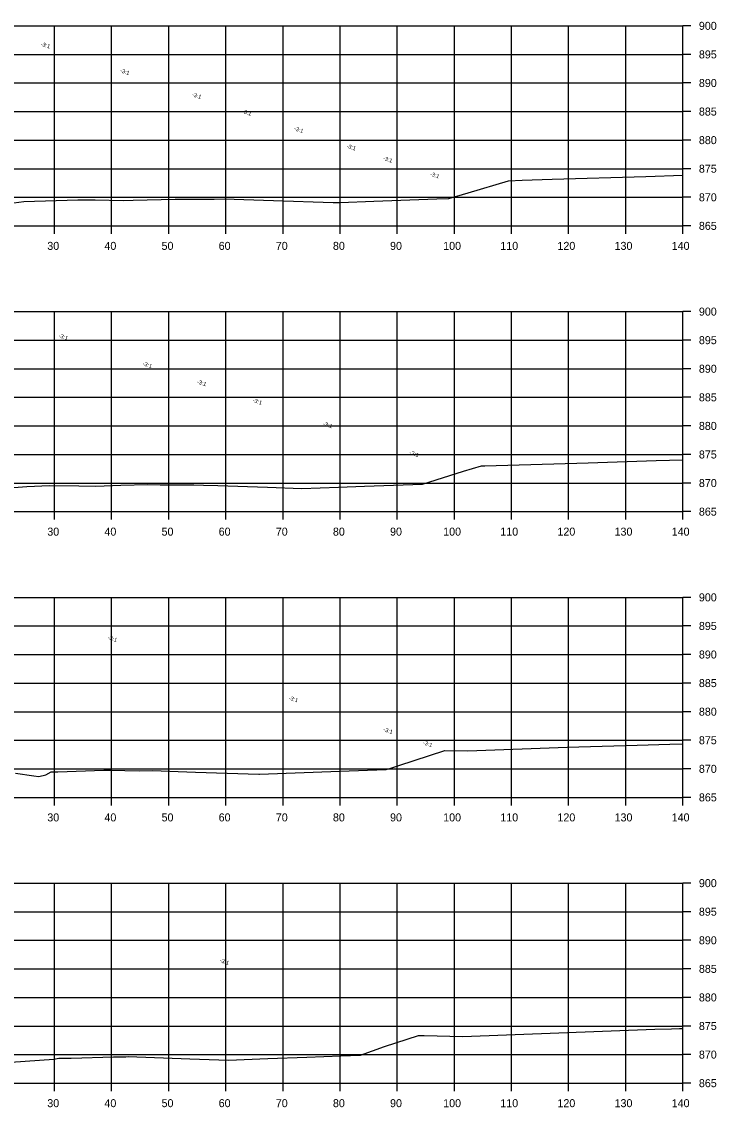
# Model space of a CAD drawing. Extents: x 1098669 to 1198896, y 698679 to 704410.
# Drawn here: x 1110915.5 to 1111037, y 704218 to 704407.9 of the extents above; entities that cross this region are included whole.
import ezdxf

# ---------------------------------------------------------------- set-up
doc = ezdxf.new("R2010")
doc.units = 0
for name, color, linetype in [('R_Axis', 7, 'Continuous'), ('R_Axis Annot', 7, 'Continuous'), ('R_Grid', 7, 'Continuous'), ('R_No Plot', 7, 'Continuous'), ('R_Xsect Slope', 7, 'Continuous')]:
    doc.layers.add(name, color=color, linetype=linetype)

msp = doc.modelspace()

# ---------------------------------------------------------------- linework, layer by layer
at = {"layer": 'R_Axis'}
for p, q in [((1111031.2, 704372.22), (1111031.2, 704407.22)), ((1111032.6, 704407.22), (1111031.2, 704407.22)), ((1111032.6, 704402.22), (1111031.2, 704402.22)), ((1111032.6, 704397.22), (1111031.2, 704397.22)), ((1111032.6, 704392.22), (1111031.2, 704392.22)), ((1111032.6, 704387.22), (1111031.2, 704387.22)), ((1111032.6, 704382.22), (1111031.2, 704382.22)), ((1111032.6, 704377.22), (1111031.2, 704377.22)), ((1110751.2, 704372.22), (1111031.2, 704372.22)), ((1110921.2, 704370.82), (1110921.2, 704372.22)), ((1110931.2, 704370.82), (1110931.2, 704372.22)), ((1110941.2, 704370.82), (1110941.2, 704372.22)), ((1110951.2, 704370.82), (1110951.2, 704372.22)), ((1110961.2, 704370.82), (1110961.2, 704372.22)), ((1110971.2, 704370.82), (1110971.2, 704372.22)), ((1110981.2, 704370.82), (1110981.2, 704372.22)), ((1110991.2, 704370.82), (1110991.2, 704372.22)), ((1111001.2, 704370.82), (1111001.2, 704372.22)), ((1111011.2, 704370.82), (1111011.2, 704372.22)), ((1111021.2, 704370.82), (1111021.2, 704372.22)), ((1111031.2, 704370.82), (1111031.2, 704372.22)), ((1111032.6, 704372.22), (1111031.2, 704372.22)), ((1111031.2, 704322.22), (1111031.2, 704357.22)), ((1111032.6, 704357.22), (1111031.2, 704357.22)), ((1111032.6, 704352.22), (1111031.2, 704352.22)), ((1111032.6, 704347.22), (1111031.2, 704347.22)), ((1111032.6, 704342.22), (1111031.2, 704342.22)), ((1111032.6, 704337.22), (1111031.2, 704337.22)), ((1111032.6, 704332.22), (1111031.2, 704332.22)), ((1111032.6, 704327.22), (1111031.2, 704327.22)), ((1110751.2, 704322.22), (1111031.2, 704322.22)), ((1110921.2, 704320.82), (1110921.2, 704322.22)), ((1110931.2, 704320.82), (1110931.2, 704322.22)), ((1110941.2, 704320.82), (1110941.2, 704322.22)), ((1110951.2, 704320.82), (1110951.2, 704322.22)), ((1110961.2, 704320.82), (1110961.2, 704322.22)), ((1110971.2, 704320.82), (1110971.2, 704322.22)), ((1110981.2, 704320.82), (1110981.2, 704322.22)), ((1110991.2, 704320.82), (1110991.2, 704322.22)), ((1111001.2, 704320.82), (1111001.2, 704322.22)), ((1111011.2, 704320.82), (1111011.2, 704322.22)), ((1111021.2, 704320.82), (1111021.2, 704322.22)), ((1111031.2, 704320.82), (1111031.2, 704322.22)), ((1111032.6, 704322.22), (1111031.2, 704322.22)), ((1111031.2, 704272.22), (1111031.2, 704307.22)), ((1111032.6, 704307.22), (1111031.2, 704307.22)), ((1111032.6, 704302.22), (1111031.2, 704302.22)), ((1111032.6, 704297.22), (1111031.2, 704297.22)), ((1111032.6, 704292.22), (1111031.2, 704292.22)), ((1111032.6, 704287.22), (1111031.2, 704287.22)), ((1111032.6, 704282.22), (1111031.2, 704282.22)), ((1111032.6, 704277.22), (1111031.2, 704277.22)), ((1110751.2, 704272.22), (1111031.2, 704272.22)), ((1110921.2, 704270.82), (1110921.2, 704272.22)), ((1110931.2, 704270.82), (1110931.2, 704272.22)), ((1110941.2, 704270.82), (1110941.2, 704272.22)), ((1110951.2, 704270.82), (1110951.2, 704272.22)), ((1110961.2, 704270.82), (1110961.2, 704272.22)), ((1110971.2, 704270.82), (1110971.2, 704272.22)), ((1110981.2, 704270.82), (1110981.2, 704272.22)), ((1110991.2, 704270.82), (1110991.2, 704272.22)), ((1111001.2, 704270.82), (1111001.2, 704272.22)), ((1111011.2, 704270.82), (1111011.2, 704272.22)), ((1111021.2, 704270.82), (1111021.2, 704272.22)), ((1111031.2, 704270.82), (1111031.2, 704272.22)), ((1111032.6, 704272.22), (1111031.2, 704272.22)), ((1111031.2, 704222.22), (1111031.2, 704257.22)), ((1111032.6, 704257.22), (1111031.2, 704257.22)), ((1111032.6, 704252.22), (1111031.2, 704252.22)), ((1111032.6, 704247.22), (1111031.2, 704247.22)), ((1111032.6, 704242.22), (1111031.2, 704242.22)), ((1111032.6, 704237.22), (1111031.2, 704237.22)), ((1111032.6, 704232.22), (1111031.2, 704232.22)), ((1111032.6, 704227.22), (1111031.2, 704227.22)), ((1110751.2, 704222.22), (1111031.2, 704222.22)), ((1110921.2, 704220.82), (1110921.2, 704222.22)), ((1110931.2, 704220.82), (1110931.2, 704222.22)), ((1110941.2, 704220.82), (1110941.2, 704222.22)), ((1110951.2, 704220.82), (1110951.2, 704222.22)), ((1110961.2, 704220.82), (1110961.2, 704222.22)), ((1110971.2, 704220.82), (1110971.2, 704222.22)), ((1110981.2, 704220.82), (1110981.2, 704222.22)), ((1110991.2, 704220.82), (1110991.2, 704222.22)), ((1111001.2, 704220.82), (1111001.2, 704222.22)), ((1111011.2, 704220.82), (1111011.2, 704222.22)), ((1111021.2, 704220.82), (1111021.2, 704222.22)), ((1111031.2, 704220.82), (1111031.2, 704222.22)), ((1111032.6, 704222.22), (1111031.2, 704222.22))]:
    msp.add_line(p, q, dxfattribs=at)
at = {"layer": 'R_Grid'}
for p, q in [((1110751.2, 704407.22), (1111031.2, 704407.22)), ((1110921.2, 704372.22), (1110921.2, 704407.22)), ((1110931.2, 704372.22), (1110931.2, 704407.22)), ((1110941.2, 704372.22), (1110941.2, 704407.22)), ((1110951.2, 704372.22), (1110951.2, 704407.22)), ((1110961.2, 704372.22), (1110961.2, 704407.22)), ((1110971.2, 704372.22), (1110971.2, 704407.22)), ((1110981.2, 704372.22), (1110981.2, 704407.22)), ((1110991.2, 704372.22), (1110991.2, 704407.22)), ((1111001.2, 704372.22), (1111001.2, 704407.22)), ((1111011.2, 704372.22), (1111011.2, 704407.22)), ((1111021.2, 704372.22), (1111021.2, 704407.22)), ((1111031.2, 704372.22), (1111031.2, 704407.22)), ((1110751.2, 704402.22), (1111031.2, 704402.22)), ((1110751.2, 704397.22), (1111031.2, 704397.22)), ((1110751.2, 704392.22), (1111031.2, 704392.22)), ((1110751.2, 704387.22), (1111031.2, 704387.22)), ((1110751.2, 704382.22), (1111031.2, 704382.22)), ((1110751.2, 704377.22), (1111031.2, 704377.22)), ((1110751.2, 704372.22), (1111031.2, 704372.22)), ((1110751.2, 704357.22), (1111031.2, 704357.22)), ((1110921.2, 704322.22), (1110921.2, 704357.22)), ((1110931.2, 704322.22), (1110931.2, 704357.22)), ((1110941.2, 704322.22), (1110941.2, 704357.22)), ((1110951.2, 704322.22), (1110951.2, 704357.22)), ((1110961.2, 704322.22), (1110961.2, 704357.22)), ((1110971.2, 704322.22), (1110971.2, 704357.22)), ((1110981.2, 704322.22), (1110981.2, 704357.22)), ((1110991.2, 704322.22), (1110991.2, 704357.22)), ((1111001.2, 704322.22), (1111001.2, 704357.22)), ((1111011.2, 704322.22), (1111011.2, 704357.22)), ((1111021.2, 704322.22), (1111021.2, 704357.22)), ((1111031.2, 704322.22), (1111031.2, 704357.22)), ((1110751.2, 704352.22), (1111031.2, 704352.22)), ((1110751.2, 704347.22), (1111031.2, 704347.22)), ((1110751.2, 704342.22), (1111031.2, 704342.22)), ((1110751.2, 704337.22), (1111031.2, 704337.22)), ((1110751.2, 704332.22), (1111031.2, 704332.22)), ((1110751.2, 704327.22), (1111031.2, 704327.22)), ((1110751.2, 704322.22), (1111031.2, 704322.22)), ((1110751.2, 704307.22), (1111031.2, 704307.22)), ((1110921.2, 704272.22), (1110921.2, 704307.22)), ((1110931.2, 704272.22), (1110931.2, 704307.22)), ((1110941.2, 704272.22), (1110941.2, 704307.22)), ((1110951.2, 704272.22), (1110951.2, 704307.22)), ((1110961.2, 704272.22), (1110961.2, 704307.22)), ((1110971.2, 704272.22), (1110971.2, 704307.22)), ((1110981.2, 704272.22), (1110981.2, 704307.22)), ((1110991.2, 704272.22), (1110991.2, 704307.22)), ((1111001.2, 704272.22), (1111001.2, 704307.22)), ((1111011.2, 704272.22), (1111011.2, 704307.22)), ((1111021.2, 704272.22), (1111021.2, 704307.22)), ((1111031.2, 704272.22), (1111031.2, 704307.22)), ((1110751.2, 704302.22), (1111031.2, 704302.22)), ((1110751.2, 704297.22), (1111031.2, 704297.22)), ((1110751.2, 704292.22), (1111031.2, 704292.22)), ((1110751.2, 704287.22), (1111031.2, 704287.22)), ((1110751.2, 704282.22), (1111031.2, 704282.22)), ((1110751.2, 704277.22), (1111031.2, 704277.22)), ((1110751.2, 704272.22), (1111031.2, 704272.22)), ((1110751.2, 704257.22), (1111031.2, 704257.22)), ((1110921.2, 704222.22), (1110921.2, 704257.22)), ((1110931.2, 704222.22), (1110931.2, 704257.22)), ((1110941.2, 704222.22), (1110941.2, 704257.22)), ((1110951.2, 704222.22), (1110951.2, 704257.22)), ((1110961.2, 704222.22), (1110961.2, 704257.22)), ((1110971.2, 704222.22), (1110971.2, 704257.22)), ((1110981.2, 704222.22), (1110981.2, 704257.22)), ((1110991.2, 704222.22), (1110991.2, 704257.22)), ((1111001.2, 704222.22), (1111001.2, 704257.22)), ((1111011.2, 704222.22), (1111011.2, 704257.22)), ((1111021.2, 704222.22), (1111021.2, 704257.22)), ((1111031.2, 704222.22), (1111031.2, 704257.22)), ((1110751.2, 704252.22), (1111031.2, 704252.22)), ((1110751.2, 704247.22), (1111031.2, 704247.22)), ((1110751.2, 704242.22), (1111031.2, 704242.22)), ((1110751.2, 704237.22), (1111031.2, 704237.22)), ((1110751.2, 704232.22), (1111031.2, 704232.22)), ((1110751.2, 704227.22), (1111031.2, 704227.22)), ((1110751.2, 704222.22), (1111031.2, 704222.22))]:
    msp.add_line(p, q, dxfattribs=at)
at = {"layer": 'R_No Plot'}
for points in [[(1110914.08, 704376.25), (1110915.86, 704376.49), (1110925.3, 704376.79), (1110928.29, 704376.77), (1110933.26, 704376.66), (1110934.99, 704376.73), (1110942.33, 704376.91), (1110942.39, 704376.9), (1110942.73, 704376.91), (1110949.15, 704376.9), (1110950.89, 704376.93), (1110959.54, 704376.64), (1110969.96, 704376.29), (1110970.7, 704376.32), (1110971.23, 704376.33), (1110977.12, 704376.54), (1110988.13, 704376.95), (1110990.24, 704377.01), (1110993.64, 704377.99), (1111000.67, 704380.09), (1111003.08, 704380.22), (1111008.32, 704380.37), (1111024.74, 704380.88), (1111031.2, 704381.1)], [(1110914.07, 704326.47), (1110915.58, 704326.54), (1110916.33, 704326.64), (1110920.32, 704326.77), (1110925.46, 704326.73), (1110928.42, 704326.67), (1110932.81, 704326.83), (1110937.54, 704326.95), (1110939.71, 704326.9), (1110945.6, 704326.92), (1110947.28, 704326.86), (1110949.78, 704326.78), (1110958.47, 704326.48), (1110964.47, 704326.28), (1110970.9, 704326.52), (1110975.46, 704326.68), (1110985.6, 704327.04), (1110992.82, 704329.29), (1110995.95, 704330.23), (1110996.55, 704330.26), (1111014.59, 704330.78), (1111026.5, 704331.15), (1111031.2, 704331.31)], [(1110914.39, 704276.47), (1110917.59, 704276), (1110918.48, 704275.87), (1110919.69, 704276.16), (1110920.64, 704276.69), (1110921.6, 704276.68), (1110921.81, 704276.68), (1110929.83, 704276.97), (1110931, 704277), (1110936.04, 704276.89), (1110938.37, 704276.9), (1110945.89, 704276.64), (1110956.97, 704276.26), (1110957.04, 704276.26), (1110957.11, 704276.26), (1110971.16, 704276.79), (1110979.27, 704277.08), (1110980.05, 704277.36), (1110981.5, 704277.83), (1110989.5, 704280.42), (1110993.53, 704280.34), (1111010.95, 704280.99), (1111023.17, 704281.33), (1111028.91, 704281.51), (1111031.2, 704281.59)], [(1110913.54, 704225.87), (1110921.08, 704226.4), (1110921.96, 704226.61), (1110924.12, 704226.6), (1110931.54, 704226.83), (1110933.7, 704226.85), (1110934.08, 704226.86), (1110944.91, 704226.48), (1110951.67, 704226.25), (1110958.56, 704226.51), (1110965.38, 704226.76), (1110971.35, 704226.99), (1110974.79, 704227.11), (1110978.97, 704228.63), (1110984.94, 704230.56), (1110985.9, 704230.54), (1110992.7, 704230.4), (1111026.31, 704231.65), (1111029.23, 704231.73), (1111030.61, 704231.77), (1111031.2, 704231.79)]]:
    msp.add_lwpolyline(points, dxfattribs=at)

# ---------------------------------------------------------------- texts
at = {"layer": 'R_Axis Annot'}
for s, p in [('900', (1111034, 704406.52)), ('895', (1111034, 704401.52)), ('890', (1111034, 704396.52)), ('885', (1111034, 704391.52)), ('880', (1111034, 704386.52)), ('875', (1111034, 704381.52)), ('870', (1111034, 704376.52)), ('865', (1111034, 704371.52)), ('30', (1110919.94, 704368.02)), ('40', (1110929.94, 704368.02)), ('50', (1110939.94, 704368.02)), ('60', (1110949.94, 704368.02)), ('70', (1110959.94, 704368.02)), ('80', (1110969.94, 704368.02)), ('90', (1110979.94, 704368.02)), ('100', (1110989.24, 704368.02)), ('110', (1110999.24, 704368.02)), ('120', (1111009.24, 704368.02)), ('130', (1111019.24, 704368.02)), ('140', (1111029.24, 704368.02)), ('900', (1111034, 704356.52)), ('895', (1111034, 704351.52)), ('890', (1111034, 704346.52)), ('885', (1111034, 704341.52)), ('880', (1111034, 704336.52)), ('875', (1111034, 704331.52)), ('870', (1111034, 704326.52)), ('865', (1111034, 704321.52)), ('30', (1110919.94, 704318.02)), ('40', (1110929.94, 704318.02)), ('50', (1110939.94, 704318.02)), ('60', (1110949.94, 704318.02)), ('70', (1110959.94, 704318.02)), ('80', (1110969.94, 704318.02)), ('90', (1110979.94, 704318.02)), ('100', (1110989.24, 704318.02)), ('110', (1110999.24, 704318.02)), ('120', (1111009.24, 704318.02)), ('130', (1111019.24, 704318.02)), ('140', (1111029.24, 704318.02)), ('900', (1111034, 704306.52)), ('895', (1111034, 704301.52)), ('890', (1111034, 704296.52)), ('885', (1111034, 704291.52)), ('880', (1111034, 704286.52)), ('875', (1111034, 704281.52)), ('870', (1111034, 704276.52)), ('865', (1111034, 704271.52)), ('30', (1110919.94, 704268.02)), ('40', (1110929.94, 704268.02)), ('50', (1110939.94, 704268.02)), ('60', (1110949.94, 704268.02)), ('70', (1110959.94, 704268.02)), ('80', (1110969.94, 704268.02)), ('90', (1110979.94, 704268.02)), ('100', (1110989.24, 704268.02)), ('110', (1110999.24, 704268.02)), ('120', (1111009.24, 704268.02)), ('130', (1111019.24, 704268.02)), ('140', (1111029.24, 704268.02)), ('900', (1111034, 704256.52)), ('895', (1111034, 704251.52)), ('890', (1111034, 704246.52)), ('885', (1111034, 704241.52)), ('880', (1111034, 704236.52)), ('875', (1111034, 704231.52)), ('870', (1111034, 704226.52)), ('865', (1111034, 704221.52)), ('30', (1110919.94, 704218.02)), ('40', (1110929.94, 704218.02)), ('50', (1110939.94, 704218.02)), ('60', (1110949.94, 704218.02)), ('70', (1110959.94, 704218.02)), ('80', (1110969.94, 704218.02)), ('90', (1110979.94, 704218.02)), ('100', (1110989.24, 704218.02)), ('110', (1110999.24, 704218.02)), ('120', (1111009.24, 704218.02)), ('130', (1111019.24, 704218.02)), ('140', (1111029.24, 704218.02))]:
    msp.add_text(s, height=1.4, dxfattribs=at).set_placement(p)
at = {"layer": 'R_Xsect Slope'}
for rotation, p in [(341.553, (1110918.73, 704403.76)), (341.548, (1110932.63, 704399.12)), (341.581, (1110945.2, 704394.93)), (341.5753, (1110953.98, 704392)), (341.5525, (1110963.06, 704388.98)), (341.579, (1110972.26, 704385.91)), (341.5475, (1110978.65, 704383.78)), (341.583, (1110986.87, 704381.04)), (341.5602, (1110921.87, 704352.74)), (341.557, (1110936.58, 704347.84)), (341.553, (1110946.08, 704344.67)), (341.548, (1110955.83, 704341.42)), (341.581, (1110968.14, 704337.32)), (341.5753, (1110983.27, 704332.28)), (341.5622, (1110930.46, 704299.92)), (341.5679, (1110962.13, 704289.36)), (341.5627, (1110978.71, 704283.83)), (341.5772, (1110985.65, 704281.52)), (341.5651, (1110950.06, 704243.41))]:
    msp.add_text('-3:1', height=0.7, rotation=rotation, dxfattribs=at).set_placement(p)

doc.saveas('drawing.dxf')
